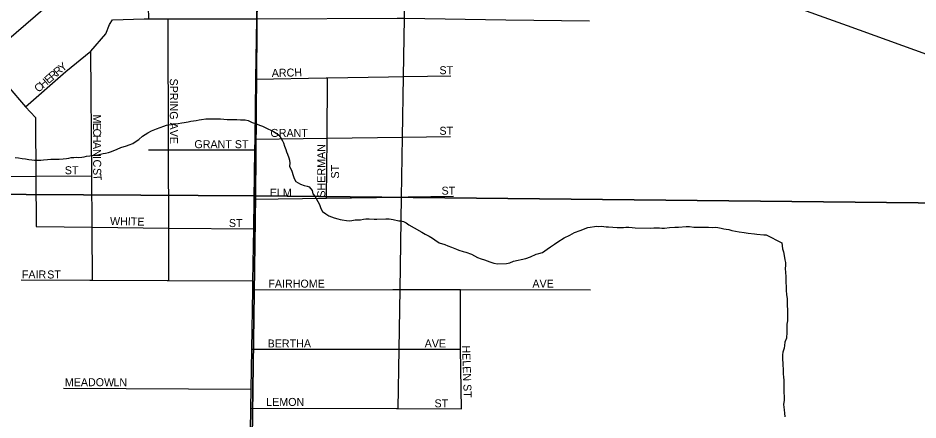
# Model space of a CAD drawing. Extents: x 1588073 to 2013523, y 1090242 to 1357120.
# Drawn here: x 1836451 to 1842074, y 1200987 to 1203498 of the extents above; entities that cross this region are included whole.
import ezdxf

# ---------------------------------------------------------------- set-up
doc = ezdxf.new("R2010")
doc.units = 0
for name, color, linetype in [('GM_X_City_Street', 7, 'Continuous'), ('GM_X_City_Street_Text', 7, 'Continuous'), ('GM_X_Minor_River', 7, 'Continuous'), ('GM_X_Rail_Line', 7, 'Continuous'), ('GM_X_Section', 7, 'Continuous'), ('GM_X_State_Route', 7, 'Continuous')]:
    doc.layers.add(name, color=color, linetype=linetype)

msp = doc.modelspace()

# ---------------------------------------------------------------- linework, layer by layer
at = {"layer": 'GM_X_City_Street'}
for points in [[(1838826.4, 1201058), (1838832.4, 1201429.3), (1838838.4, 1201801.9), (1838847.7, 1202379.7), (1838853.7, 1202753.3), (1838859.8, 1203132.4), (1838865.7, 1203496.6), (1838865.6, 1204054.6), (1838865.6, 1204493.9), (1838865.6, 1204582.8), (1838856.2, 1204806.1), (1838856.2, 1204807.2)], [(1836061.3, 1203075.9), (1836234.8, 1203231.8), (1836242.3, 1203238.3), (1837252.7, 1204112), (1837268.4, 1204125.6), (1837308.8, 1204145.2), (1837321.4, 1204151.3), (1837322.9, 1204152)], [(1837268.1, 1203492.1), (1837262.5, 1203719.8), (1837252.7, 1204112)], [(1836497.7, 1202942.9), (1836748.8, 1203164.9), (1836906.4, 1203290.4), (1836999.8, 1203398.6), (1837023.3, 1203457), (1837040.7, 1203486.1), (1837239.4, 1203492), (1837268.1, 1203492.1), (1837388.6, 1203492.5), (1837880.5, 1203493.8), (1837881.7, 1203493.8)], [(1837394.1, 1201859.2), (1837393, 1202186.1), (1837391.4, 1202674.4), (1837388.6, 1203492.5)], [(1837881.7, 1203493.8), (1837943.1, 1203494), (1838818.8, 1203496.4), (1838820.9, 1203496.5)], [(1838820.9, 1203496.5), (1838865.7, 1203496.6), (1839498.1, 1203487.4), (1839499.1, 1203487.4)], [(1839499.1, 1203487.4), (1840020.8, 1203479.8)], [(1836914, 1202178.8), (1836914, 1202179), (1836913.9, 1202191.5), (1836911.7, 1202512.2), (1836906.4, 1203290.4)], [(1836274.1, 1203201.4), (1836497.7, 1202942.9), (1836559.6, 1202875.6), (1836559.7, 1202855.3), (1836559.8, 1202853.3)], [(1837937.4, 1203116.5), (1838375.7, 1203124.1)], [(1838375.7, 1203124.1), (1838375.8, 1203124.1), (1838385.2, 1203124.2), (1838765.4, 1203130.8)], [(1838378.5, 1202373.3), (1838381.8, 1202747), (1838385.2, 1203124.2)], [(1838765.4, 1203130.8), (1838765.4, 1203130.8), (1838859.8, 1203132.4), (1839008.9, 1203135)], [(1839008.9, 1203135), (1839008.9, 1203135), (1839155, 1203137.5)], [(1836559.8, 1202853.3), (1836562.5, 1202510.1), (1836565, 1202195.3)], [(1837931.8, 1202740.9), (1838381.8, 1202747), (1838853.7, 1202753.3), (1839153.3, 1202757.4)], [(1837265.8, 1202674.3), (1837391.4, 1202674.4), (1837930.8, 1202674.6)], [(1835233.2, 1202502), (1835424, 1202503.1), (1836562.5, 1202510.1), (1836911.7, 1202512.2)], [(1837926.1, 1202367.2), (1838378.5, 1202373.3), (1838847.7, 1202379.7), (1838889.4, 1202380.3), (1838889.4, 1202380.3)], [(1838889.4, 1202380.3), (1839172.7, 1202384.1)], [(1836565, 1202195.3), (1836913.9, 1202191.5), (1837393, 1202186.1), (1837923.3, 1202180.2)], [(1836916.1, 1201861.1), (1836914, 1202178.8)], [(1836471.3, 1201863), (1836900.1, 1201861.2)], [(1836900.1, 1201861.2), (1836900.1, 1201861.2), (1836916.1, 1201861.1), (1837382.5, 1201859.2)], [(1837382.5, 1201859.2), (1837382.5, 1201859.2), (1837394.1, 1201859.2), (1837918.5, 1201857)], [(1837917.6, 1201799), (1838792.7, 1201801.7)], [(1838792.7, 1201801.7), (1838793.8, 1201801.7), (1838838.4, 1201801.9), (1839216.4, 1201803), (1840028.2, 1201800.3)], [(1839220.8, 1201057.2), (1839216.4, 1201429.2), (1839216.4, 1201803)], [(1837912.1, 1201429.6), (1838832.4, 1201429.3), (1839216.4, 1201429.2)], [(1836734.6, 1201184.5), (1837908.3, 1201180.2)], [(1837906.5, 1201059.9), (1838816.4, 1201058), (1838816.4, 1201058)], [(1838816.4, 1201058), (1838826.4, 1201058), (1839220.8, 1201057.2)]]:
    msp.add_lwpolyline(points, dxfattribs=at)
at = {"layer": 'GM_X_Minor_River'}
for points in [[(1836433.9, 1202626), (1836453.9, 1202623.8), (1836475.9, 1202619.6), (1836497.9, 1202617.4), (1836517.9, 1202613.2), (1836537.9, 1202613), (1836553.9, 1202610.9), (1836594, 1202610.5), (1836610, 1202612.4), (1836634, 1202614.2), (1836656.1, 1202616), (1836688.1, 1202615.7), (1836708.1, 1202615.5), (1836732.2, 1202619.3), (1836754.2, 1202621.1), (1836768.3, 1202623), (1836782.3, 1202626.9), (1836800.3, 1202626.7), (1836816.4, 1202628.6), (1836830.4, 1202626.5), (1836850.4, 1202628.3), (1836864.4, 1202630.2), (1836878.5, 1202634.1), (1836898.6, 1202637.9), (1836920.6, 1202641.7), (1836948.7, 1202643.5), (1836966.7, 1202647.3), (1836982.8, 1202651.2), (1836996.8, 1202653.1), (1837016.9, 1202658.9), (1837034.9, 1202664.8), (1837071.1, 1202678.5), (1837093.2, 1202688.3), (1837129.3, 1202700), (1837145.4, 1202705.9), (1837167.5, 1202713.7), (1837189.7, 1202729.5), (1837205.8, 1202739.4), (1837228, 1202759.3), (1837262.2, 1202781), (1837284.3, 1202792.8), (1837316.5, 1202806.6), (1837338.6, 1202814.4), (1837362.6, 1202822.2), (1837378.7, 1202828.1), (1837408.8, 1202833.8), (1837422.8, 1202837.7), (1837436.9, 1202837.6), (1837450.9, 1202839.5), (1837475, 1202843.3), (1837489, 1202845.2), (1837513.1, 1202849), (1837531.1, 1202852.8), (1837547.1, 1202854.7), (1837563.2, 1202858.5), (1837583.2, 1202862.4), (1837597.3, 1202864.2), (1837623.3, 1202868), (1837715.4, 1202867.2), (1837757.5, 1202864.8), (1837817.5, 1202864.3), (1837841.5, 1202862.1), (1837869.6, 1202861.8), (1837889.6, 1202857.6), (1837913.5, 1202845.4), (1837935.5, 1202839.2), (1837959.4, 1202829), (1837977.4, 1202822.8), (1837995.3, 1202814.6), (1838011.3, 1202806.5), (1838031.2, 1202798.3), (1838047.2, 1202788.1), (1838067.1, 1202775.9), (1838081, 1202765.8), (1838092.9, 1202749.6), (1838102.8, 1202731.5), (1838110.6, 1202717.4), (1838116.5, 1202697.3), (1838124.3, 1202677.2), (1838128.2, 1202661.1), (1838134.1, 1202647), (1838141.9, 1202624.9), (1838147.8, 1202610.8), (1838149.6, 1202590.8), (1838147.5, 1202572.7)], [(1838147.5, 1202572.7), (1838161.2, 1202540.5), (1838171, 1202514.4), (1838176.9, 1202496.3), (1838186.7, 1202476.2), (1838200.7, 1202468), (1838216.6, 1202459.9), (1838238.6, 1202451.6), (1838256.6, 1202447.5), (1838270.5, 1202443.3), (1838288.4, 1202421.1), (1838292.2, 1202399.1), (1838306.1, 1202384.9), (1838323.8, 1202352.7), (1838333.7, 1202332.5), (1838343.5, 1202308.4), (1838353.3, 1202290.3), (1838373.2, 1202274.1), (1838393.2, 1202261.9), (1838409.1, 1202255.7), (1838427.1, 1202249.5), (1838449.1, 1202243.3), (1838463, 1202239.2), (1838477, 1202237.1), (1838503, 1202232.8), (1838519, 1202230.7), (1838537.1, 1202232.5), (1838557.1, 1202236.3), (1838577.2, 1202238.2), (1838591.2, 1202238.1), (1838609.2, 1202241.9), (1838623.3, 1202243.8), (1838645.3, 1202243.6), (1838675.3, 1202241.3), (1838693.3, 1202241.2), (1838749.4, 1202242.7), (1838769.4, 1202242.5), (1838795.4, 1202238.3), (1838829.4, 1202231.9), (1838843.4, 1202231.8), (1838859.4, 1202227.7), (1838875.3, 1202217.5), (1838893.3, 1202205.3), (1838925.2, 1202187), (1838973, 1202160.5), (1838994.9, 1202148.3), (1839018.8, 1202136.1), (1839040.7, 1202121.8), (1839054.7, 1202111.7), (1839082.6, 1202093.4), (1839118.5, 1202083.1), (1839136.5, 1202074.9), (1839158.4, 1202066.7), (1839190.4, 1202054.3), (1839204.3, 1202048.2), (1839232.3, 1202039.9), (1839248.3, 1202035.8), (1839284.2, 1202023.4), (1839302.1, 1202011.3), (1839322.1, 1202001.1), (1839344, 1201992.9), (1839366, 1201986.6), (1839397.9, 1201974.3), (1839423.9, 1201966.1), (1839445.9, 1201961.9), (1839502, 1201963.4), (1839524, 1201969.2), (1839546.1, 1201979.1), (1839624.4, 1201996.4), (1839652.5, 1202006.2), (1839688.7, 1202021.9), (1839704.7, 1202027.8), (1839728.8, 1202033.6), (1839757, 1202053.4), (1839777.2, 1202069.2), (1839803.3, 1202085), (1839823.5, 1202098.9), (1839863.7, 1202124.6), (1839897.9, 1202142.3), (1839928.1, 1202158.1), (1839962.2, 1202169.8), (1840010.4, 1202189.4), (1840066.6, 1202196.9), (1840080.6, 1202194.8), (1840096.6, 1202196.7), (1840126.6, 1202194.4), (1840140.6, 1202194.3), (1840166.7, 1202192.1), (1840194.7, 1202189.8), (1840234.7, 1202189.5), (1840248.7, 1202191.3), (1840266.8, 1202191.2), (1840288.8, 1202189), (1840306.8, 1202186.8), (1840402.9, 1202186), (1840422.9, 1202187.8), (1840445, 1202187.6), (1840459, 1202187.5), (1840473, 1202185.3), (1840491, 1202185.2), (1840521.1, 1202188.9)], [(1840521.1, 1202188.9), (1840555.1, 1202190.6), (1840577.1, 1202192.4), (1840625.2, 1202196), (1840645.3, 1202195.8), (1840673.3, 1202191.6), (1840765.4, 1202190.8), (1840791.4, 1202188.5), (1840809.4, 1202190.4), (1840823.4, 1202188.3), (1840843.4, 1202186.1), (1840861.4, 1202181.9), (1840875.4, 1202179.8), (1840891.4, 1202177.6), (1840911.4, 1202171.4), (1840933.4, 1202167.2), (1840957.3, 1202163), (1840987.3, 1202158.8), (1841013.3, 1202154.5), (1841053.4, 1202150.1), (1841067.4, 1202148), (1841111.4, 1202143.6), (1841125.4, 1202143.5), (1841223.1, 1202094.5), (1841226.8, 1202056.4), (1841232.6, 1202036.3), (1841240.3, 1202002.2), (1841242.2, 1201988.1), (1841246.1, 1201970), (1841245.9, 1201952), (1841243.8, 1201934), (1841245.5, 1201907.9), (1841247.3, 1201883.8), (1841249.1, 1201851.7), (1841250.8, 1201813.6), (1841250.6, 1201797.6), (1841252.4, 1201769.5), (1841256.2, 1201745.4), (1841255.9, 1201715.4), (1841259.5, 1201663.2), (1841259, 1201607.1), (1841254.9, 1201585.1), (1841254.4, 1201535), (1841252.1, 1201496.9), (1841241.9, 1201472.9), (1841239.7, 1201452.9), (1841237.6, 1201434.9), (1841229.4, 1201410.9), (1841227.2, 1201392.9), (1841227, 1201368.8), (1841228.7, 1201336.7), (1841232.4, 1201296.6), (1841232.2, 1201272.6), (1841234.1, 1201256.5), (1841235.9, 1201234.4), (1841235.7, 1201206.4), (1841235.2, 1201156.3), (1841237.1, 1201136.2), (1841236.9, 1201110.1), (1841234.6, 1201084.1), (1841238.3, 1201050), (1841240.2, 1201029.9), (1841242, 1201005.9)]]:
    msp.add_lwpolyline(points, dxfattribs=at)
at = {"layer": 'GM_X_Rail_Line'}
msp.add_lwpolyline([(1838295.8, 1205278.4), (1838395.5, 1205246.2), (1838443.2, 1205228.3), (1838505.6, 1205202.4), (1838599.1, 1205156.7), (1838940.3, 1204987.1), (1839008.8, 1204945.8), (1839081.1, 1204899.4), (1839172.3, 1204834.8), (1839246.2, 1204765.5), (1839530.1, 1204469.3), (1839591, 1204412.7), (1839662.6, 1204349.7), (1839746.2, 1204282.8), (1839834.4, 1204216), (1839923.9, 1204152.8), (1840037.9, 1204081.2), (1840164.5, 1204009.6), (1840260.7, 1203961.2), (1840360.8, 1203915.4), (1840455.6, 1203875), (1841630.6, 1203450.6), (1842894.4, 1202995.1)], dxfattribs=at)
at = {"layer": 'GM_X_Section'}
for points in [[(1837979, 1207751.4), (1837935.3, 1202386.5), (1832556.3, 1202418.4), (1832640.2, 1207803)], [(1843328, 1207707.7), (1843258.1, 1202330.9), (1837935.3, 1202386.5), (1837979, 1207751.4)], [(1832556.3, 1202418.4), (1837935.3, 1202386.5), (1837861.8, 1197091.9), (1832498.9, 1197101.7)], [(1843258.1, 1202330.9), (1843180.8, 1197072.2), (1837861.8, 1197091.9), (1837935.3, 1202386.5)]]:
    msp.add_lwpolyline(points, close=True, dxfattribs=at)
at = {"layer": 'GM_X_State_Route'}
for points in [[(1837918.1, 1201829.3), (1837918.5, 1201857), (1837923.3, 1202180.2), (1837926.1, 1202367.2), (1837930.8, 1202674.6), (1837931.8, 1202740.9), (1837937.4, 1203116.5), (1837943.1, 1203494), (1837949.8, 1203942.9), (1837950.1, 1203960.3)], [(1837855.8, 1197671), (1837858.7, 1197867.1), (1837906.5, 1201059.9), (1837908.3, 1201180.2), (1837912.1, 1201429.6), (1837917.6, 1201799), (1837918.1, 1201829.3)]]:
    msp.add_lwpolyline(points, dxfattribs=at)

# ---------------------------------------------------------------- texts
at = {"layer": 'GM_X_City_Street_Text'}
for s, rotation, p in [('Y', 39.73, (1836728.3, 1203159.4)), ('R', 40.8067, (1836668.5, 1203107.8)), ('R', 40.8067, (1836698.5, 1203133.7)), ('ARCH', 1.4709, (1838036.5, 1203129.2)), ('ST', 0, (1839083.9, 1203146.9)), ('H', 40.8076, (1836608.6, 1203056)), ('E', 40.8143, (1836641.9, 1203084.8)), ('SPRING AVE', 270, (1837399.4, 1203119.8)), ('C', 40.8067, (1836578.6, 1203030.1)), ('M', 270.1093, (1836919.8, 1202895.4)), ('E', 270.1093, (1836919.9, 1202842.6)), ('C', 270.0971, (1836919.9, 1202807.4)), ('GRANT', 0, (1838027.9, 1202755.2)), ('ST', 0, (1839083.9, 1202768.5)), ('H', 270.1054, (1836920, 1202767.8)), ('A', 270.1093, (1836920.1, 1202723.8)), ('GRANT ST', 0, (1837552.8, 1202684.8)), ('N', 270.1093, (1836920.2, 1202679.8)), ('SHERMAN', 90, (1838370.5, 1202376.2)), ('C', 270.1128, (1836920.3, 1202613.8)), ('I', 270.0874, (1836920.2, 1202635.8)), ('ST', 0, (1836743.1, 1202522.1)), ('S', 270.1022, (1836920.4, 1202561)), ('ST', 90, (1838456.6, 1202495)), ('T', 275.0445, (1836920.7, 1202521.1)), ('ST', 0, (1839097.1, 1202394.4)), ('ELM', 0, (1838023.5, 1202381.2)), ('WHITE', 358.7276, (1837025, 1202205.2)), ('ST', 0, (1837768.4, 1202192)), ('FAIR', 0, (1836474.8, 1201870.9)), ('ST', 0, (1836633.2, 1201870.9)), ('FAIRHOME', 0, (1838014.8, 1201813.6)), ('AVE', 0, (1839664.7, 1201813.6)), ('BERTHA', 0, (1838010.4, 1201439.7)), ('AVE', 0, (1838991.6, 1201439.7)), ('HELEN ST', 271.7938, (1839225.4, 1201451.8)), ('MEADOW', 0, (1836743.1, 1201197.7)), ('LN', 0, (1837046.7, 1201197.6)), ('LEMON', 0, (1838001.5, 1201074.5)), ('ST', 0, (1839053.1, 1201065.6))]:
    msp.add_text(s, height=50, rotation=rotation, dxfattribs=at).set_placement(p)

doc.saveas('drawing.dxf')
